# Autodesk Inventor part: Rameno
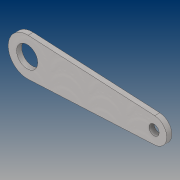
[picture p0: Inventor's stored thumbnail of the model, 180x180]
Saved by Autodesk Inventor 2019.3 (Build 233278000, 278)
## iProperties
Created: 2019-02
Part Number: Rameno
Material: Ocel, měkká, svařovaná
Document SubType Name: Modeling
Designer: B-hon
Density: 7.85 g/cm^3
Appearance: Svar – měkká ocel
Author: B-hon
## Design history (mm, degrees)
sketch "Náčrt1"
  geometry: L1 (1.125, 22.472)-(150.75, 14.981); L2 (1.125, -22.472)-(150.75, -14.981); C1 r 12.5 at (0, 0); C2 r 6 at (150, 0); A1 r 22.5 centre (0, 0) between (1.125, 22.472) and (1.125, -22.472); A2 r 15 centre (150, 0) between (150.75, -14.981) and (150.75, 14.981); 1 further point
  constraints: 4 centre point, 4 end point, 4 point on circle, 4 tangent, 3 coincident, 1 horizontal alignment
  dimensions: "d0" = 25 diameter of C1; "d1" = 12 diameter of C2; "d2" = 45 diameter of A1; "d3" = 30 diameter of A2; "d4" = 150 distance of C2.centre C1.centre
extrude "Vysunutí1" new body sketch "Náčrt1" distance "d5" = 6; taper "d6" = 0 deg
node "Těleso1"
